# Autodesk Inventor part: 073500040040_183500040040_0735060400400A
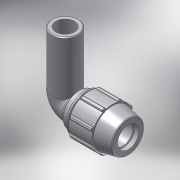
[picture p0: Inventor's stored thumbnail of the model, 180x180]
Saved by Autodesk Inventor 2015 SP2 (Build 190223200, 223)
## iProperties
Created: 2017-02
Part Number: 073500040040_183500040040_0735060400400A
Material: PVC-Piping
Description: PLASSON 90° ELBOW ADAPTOR 40-40
Document SubType Name: Modeling
Designer: KIM
Mass: 92.6774 g
Surface Area: 199.44 cm^2
Volume: 66.1981 cm^3
Density: 1.4 g/cm^3
Appearance: Smooth - White
Author: KIM
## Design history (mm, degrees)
derived "07350.ipt"
feature "Solid1::07350.ipt"
tag "TaggingFeature1"
body "Solid1"
other parameters: "d4" = 9.83333, "d5" = 29.5, "d7" = 82, "d11" = 3.93333, "d13" = 120 deg, "d15" = 12 deg, "d16" = 71.34, "d18" = 2, "d19" = 35 deg, "d20" = 17.5 deg, "d21" = 76.26, "d23" = 0, "d25" = 360 deg, "d27" = 1.64, "d33" = 0.8, "d42" = 43.66, "d43" = 2.46, "d46" = 1.2, "d51" = 118, "d68" = 3.93333, "d72" = 106, "d76" = 28, "d79" = 16, "d80" = 1.2, "d91" = 61.5, "d93" = 84, "d95" = 28, "d96" = 9.83333, "d97" = 50 deg, "d98" = 63.6, "d99" = 0, "d100" = 0, "E_" = 82, "A_" = 118, "l_" = 84, "A_1" = 106
